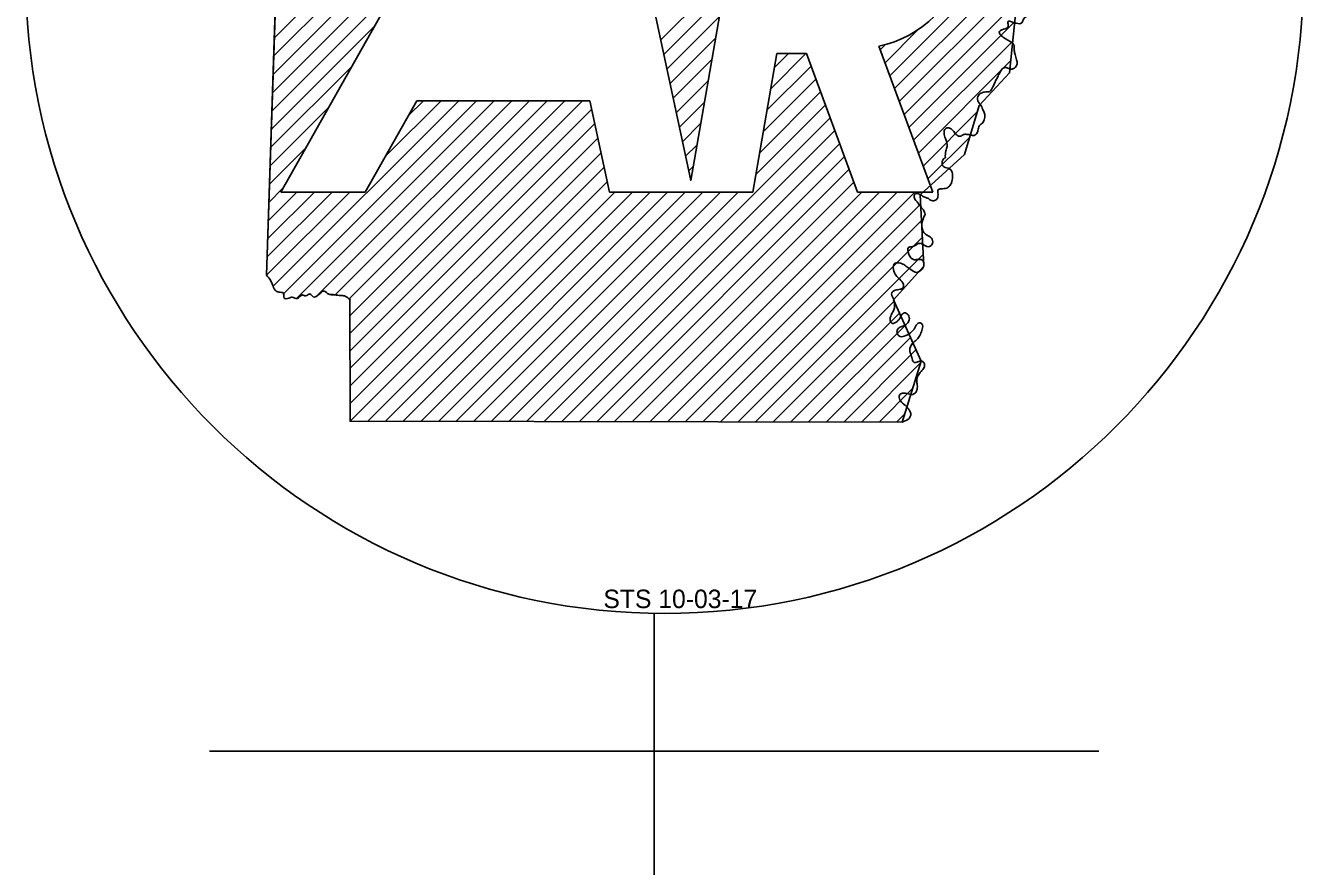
# Model space of a CAD drawing. Extents: x 1334737.7 to 1334827.2, y 402732.3 to 402753.5.
# Drawn here: x 1334746.2631 to 1334746.5859, y 402747.8449 to 402748.0573 of the extents above; entities that cross this region are included whole.
import ezdxf

# ---------------------------------------------------------------- set-up
doc = ezdxf.new("R2010")
doc.units = 0
doc.layers.add('R_Dimension', color=7, linetype='Continuous')
doc.layers.add('R_Draft', color=7, linetype='Continuous')

msp = doc.modelspace()

# ---------------------------------------------------------------- linework, layer by layer
at = {"layer": 'R_Dimension'}
for p, q in [((1334746.3259, 402748.05411), (1334746.38042, 402748.10863)), ((1334746.32575, 402748.04949), (1334746.3746, 402748.09834)), ((1334746.48142, 402748.04458), (1334746.53088, 402748.09403)), ((1334746.48263, 402748.04133), (1334746.53171, 402748.09041)), ((1334746.3256, 402748.04488), (1334746.36878, 402748.08806)), ((1334746.48383, 402748.03807), (1334746.53255, 402748.08678)), ((1334746.48504, 402748.03481), (1334746.53338, 402748.08315)), ((1334746.32544, 402748.04027), (1334746.36295, 402748.07778)), ((1334746.42355, 402748.05362), (1334746.44022, 402748.07029)), ((1334746.32529, 402748.03565), (1334746.35713, 402748.06749)), ((1334746.42434, 402748.04995), (1334746.43928, 402748.06489)), ((1334746.32514, 402748.03104), (1334746.35131, 402748.05721)), ((1334746.42512, 402748.04627), (1334746.43834, 402748.05949)), ((1334746.48624, 402748.03155), (1334746.513, 402748.05831)), ((1334746.42591, 402748.0426), (1334746.4374, 402748.05409)), ((1334746.48022, 402748.04784), (1334746.48871, 402748.05633)), ((1334746.47902, 402748.0511), (1334746.48037, 402748.05245)), ((1334746.48744, 402748.0283), (1334746.5125, 402748.05335)), ((1334746.4267, 402748.03892), (1334746.43646, 402748.04868)), ((1334746.45134, 402748.04126), (1334746.46025, 402748.05017)), ((1334746.45228, 402748.04666), (1334746.45579, 402748.05017)), ((1334746.48865, 402748.02504), (1334746.512, 402748.04839)), ((1334746.32498, 402748.02643), (1334746.34548, 402748.04693)), ((1334746.45039, 402748.03586), (1334746.46155, 402748.04701)), ((1334746.42748, 402748.03525), (1334746.43552, 402748.04328)), ((1334746.44945, 402748.03045), (1334746.46275, 402748.04375)), ((1334746.32564, 402747.9914), (1334746.37253, 402748.03828)), ((1334746.3283, 402747.98959), (1334746.37699, 402748.03828)), ((1334746.3315, 402747.98833), (1334746.38145, 402748.03828)), ((1334746.3368, 402747.98917), (1334746.38591, 402748.03828)), ((1334746.34133, 402747.98924), (1334746.39037, 402748.03828)), ((1334746.34482, 402747.98828), (1334746.39483, 402748.03828)), ((1334746.34497, 402747.98396), (1334746.39929, 402748.03828)), ((1334746.34498, 402747.97951), (1334746.40375, 402748.03828)), ((1334746.35394, 402748.02416), (1334746.36807, 402748.03828)), ((1334746.35977, 402748.03444), (1334746.36361, 402748.03828)), ((1334746.42827, 402748.03157), (1334746.43458, 402748.03788)), ((1334746.44851, 402748.02505), (1334746.46395, 402748.04049)), ((1334746.32483, 402748.02181), (1334746.33966, 402748.03664)), ((1334746.34499, 402747.97506), (1334746.4061, 402748.03617)), ((1334746.44757, 402748.01965), (1334746.46516, 402748.03724)), ((1334746.48985, 402748.02178), (1334746.50353, 402748.03546)), ((1334746.34501, 402747.97062), (1334746.40689, 402748.0325)), ((1334746.38964, 402747.95726), (1334746.46636, 402748.03398)), ((1334746.42905, 402748.0279), (1334746.43363, 402748.03248)), ((1334746.34502, 402747.96617), (1334746.40767, 402748.02882)), ((1334746.39409, 402747.95725), (1334746.46756, 402748.03072)), ((1334746.49105, 402748.01852), (1334746.50162, 402748.02909)), ((1334746.32468, 402748.0172), (1334746.33384, 402748.02636)), ((1334746.34503, 402747.96172), (1334746.40846, 402748.02515)), ((1334746.39854, 402747.95724), (1334746.46877, 402748.02747)), ((1334746.42984, 402748.02423), (1334746.43269, 402748.02708)), ((1334746.3451, 402747.95733), (1334746.40925, 402748.02147)), ((1334746.403, 402747.95724), (1334746.46997, 402748.02421)), ((1334746.43063, 402748.02055), (1334746.43175, 402748.02167)), ((1334746.40745, 402747.95723), (1334746.47117, 402748.02095)), ((1334746.32398, 402747.9942), (1334746.34501, 402748.01522)), ((1334746.32406, 402747.99874), (1334746.34055, 402748.01522)), ((1334746.32422, 402748.00336), (1334746.33609, 402748.01522)), ((1334746.32437, 402748.00797), (1334746.33163, 402748.01522)), ((1334746.32452, 402748.01258), (1334746.32801, 402748.01607)), ((1334746.34956, 402747.95732), (1334746.41003, 402748.0178)), ((1334746.35401, 402747.95732), (1334746.41192, 402748.01522)), ((1334746.35846, 402747.95731), (1334746.41638, 402748.01522)), ((1334746.36292, 402747.9573), (1334746.42084, 402748.01522)), ((1334746.36737, 402747.95729), (1334746.4253, 402748.01522)), ((1334746.37182, 402747.95729), (1334746.42976, 402748.01522)), ((1334746.37628, 402747.95728), (1334746.43422, 402748.01522)), ((1334746.38073, 402747.95727), (1334746.43868, 402748.01522)), ((1334746.38518, 402747.95726), (1334746.44314, 402748.01522)), ((1334746.4119, 402747.95722), (1334746.47238, 402748.01769)), ((1334746.41636, 402747.95721), (1334746.47437, 402748.01522)), ((1334746.42081, 402747.95721), (1334746.47883, 402748.01522)), ((1334746.42527, 402747.9572), (1334746.48329, 402748.01522)), ((1334746.42972, 402747.95719), (1334746.48775, 402748.01522)), ((1334746.43417, 402747.95718), (1334746.48924, 402748.01226)), ((1334746.43863, 402747.95718), (1334746.48944, 402748.008)), ((1334746.44308, 402747.95717), (1334746.48964, 402748.00374)), ((1334746.44753, 402747.95716), (1334746.48984, 402747.99947)), ((1334746.45199, 402747.95716), (1334746.48252, 402747.98769)), ((1334746.45644, 402747.95715), (1334746.48389, 402747.9846)), ((1334746.46089, 402747.95714), (1334746.48527, 402747.98152)), ((1334746.46535, 402747.95713), (1334746.48665, 402747.97844)), ((1334746.4698, 402747.95713), (1334746.48803, 402747.97535)), ((1334746.47425, 402747.95712), (1334746.48918, 402747.97204)), ((1334746.47871, 402747.95711), (1334746.48716, 402747.96556)), ((1334746.48316, 402747.9571), (1334746.48514, 402747.95909))]:
    msp.add_line(p, q, dxfattribs=at)
at = {"layer": 'R_Draft'}
for p, q in [((1334746.32753, 402748.01522), (1334746.38976, 402748.12512)), ((1334746.47867, 402748.05204), (1334746.49227, 402748.01522)), ((1334746.46038, 402748.05017), (1334746.45289, 402748.05017)), ((1334746.47329, 402748.01522), (1334746.46038, 402748.05017)), ((1334746.36194, 402748.03828), (1334746.34888, 402748.01522)), ((1334746.40565, 402748.03828), (1334746.36194, 402748.03828)), ((1334746.34888, 402748.01522), (1334746.32753, 402748.01522)), ((1334746.4468, 402748.01522), (1334746.41058, 402748.01522)), ((1334746.49227, 402748.01522), (1334746.47329, 402748.01522)), ((1334746.42189, 402747.49925), (1334746.42189, 402747.90883)), ((1334746.30953, 402747.87402), (1334746.53422, 402747.87402))]:
    msp.add_line(p, q, dxfattribs=at)
for points in [[(1334746.32392, 402747.99425), (1334746.32734, 402748.0975), (1334746.31946, 402748.16075)], [(1334746.54759, 402748.13423), (1334746.55291, 402748.12866), (1334746.53963, 402748.11775), (1334746.54107, 402748.10673), (1334746.52968, 402748.09922), (1334746.53358, 402748.08228), (1334746.5248, 402748.07428), (1334746.52402, 402748.06557), (1334746.51334, 402748.06173), (1334746.51168, 402748.0453), (1334746.50402, 402748.03709), (1334746.50031, 402748.02472), (1334746.48914, 402748.0145), (1334746.48999, 402747.99646), (1334746.4824, 402747.98795), (1334746.48931, 402747.97247), (1334746.48452, 402747.9571)], [(1334746.40825, 402748.12512), (1334746.43114, 402748.01816), (1334746.44578, 402748.10219)], [(1334746.32393, 402747.99424), (1334746.32626, 402748.06508)], [(1334746.45289, 402748.05017), (1334746.4468, 402748.01522)], [(1334746.41058, 402748.01522), (1334746.40565, 402748.03828)], [(1334746.48452, 402747.9571), (1334746.34504, 402747.95733), (1334746.34496, 402747.98812)], [(1334746.48451, 402747.95708), (1334746.34504, 402747.95733), (1334746.34498, 402747.98813)]]:
    msp.add_lwpolyline(points, dxfattribs=at)
msp.add_ellipse((1334746.4245, 402748.07024), major_axis=(0.16144, 0), ratio=0.999976, dxfattribs=at)
msp.add_ellipse((1334746.47293, 402748.07936), major_axis=(-0.02792, 0), ratio=0.999987, start_param=1.777838, end_param=4.099264, dxfattribs=at)
for points in [[(1334746.51656, 402748.05989), (1334746.51524, 402748.05888), (1334746.51464, 402748.05783), (1334746.51125, 402748.05814), (1334746.51135, 402748.05695), (1334746.51014, 402748.05632), (1334746.50907, 402748.05555), (1334746.50968, 402748.05462), (1334746.51083, 402748.05379), (1334746.51197, 402748.05315), (1334746.51268, 402748.05251), (1334746.51287, 402748.05092), (1334746.51308, 402748.04995), (1334746.51345, 402748.04856), (1334746.5136, 402748.04763), (1334746.51291, 402748.0465), (1334746.51211, 402748.04626), (1334746.51129, 402748.04653), (1334746.5103, 402748.0466), (1334746.5095, 402748.04586), (1334746.50893, 402748.04478), (1334746.50837, 402748.04369), (1334746.50793, 402748.0428), (1334746.50748, 402748.0418), (1334746.50669, 402748.04064), (1334746.50567, 402748.04048), (1334746.50444, 402748.04017), (1334746.50371, 402748.03935), (1334746.50383, 402748.03793), (1334746.50452, 402748.03698), (1334746.50504, 402748.03579), (1334746.50541, 402748.03477), (1334746.50525, 402748.03348), (1334746.50472, 402748.03251), (1334746.50402, 402748.03193), (1334746.50371, 402748.03073), (1334746.50321, 402748.0298), (1334746.50276, 402748.02952), (1334746.50186, 402748.02961), (1334746.50087, 402748.02978), (1334746.50003, 402748.02971), (1334746.49924, 402748.02929), (1334746.49842, 402748.02956), (1334746.49759, 402748.03046), (1334746.4969, 402748.03115), (1334746.49613, 402748.03143), (1334746.49532, 402748.03101), (1334746.4952, 402748.02973), (1334746.49559, 402748.02846), (1334746.49592, 402748.02669), (1334746.49559, 402748.02565), (1334746.49547, 402748.02386)], [(1334746.49547, 402748.02386), (1334746.49537, 402748.02382), (1334746.49469, 402748.02296), (1334746.49506, 402748.02161), (1334746.49655, 402748.02109), (1334746.49723, 402748.0198), (1334746.49726, 402748.01866), (1334746.49679, 402748.01709), (1334746.49609, 402748.01635), (1334746.49477, 402748.01605), (1334746.49375, 402748.01587), (1334746.4936, 402748.01412), (1334746.49312, 402748.01324), (1334746.49233, 402748.01298), (1334746.49118, 402748.01354), (1334746.49049, 402748.01384), (1334746.48966, 402748.01421), (1334746.48859, 402748.01482), (1334746.48778, 402748.01471), (1334746.48801, 402748.01305), (1334746.48809, 402748.01298), (1334746.48901, 402748.01172), (1334746.48991, 402748.01072), (1334746.49033, 402748.00955)], [(1334746.49547, 402748.02386), (1334746.49537, 402748.02382), (1334746.49469, 402748.02296), (1334746.49506, 402748.02161), (1334746.49655, 402748.02109), (1334746.49723, 402748.0198), (1334746.49726, 402748.01866), (1334746.49679, 402748.01709), (1334746.49609, 402748.01635), (1334746.49477, 402748.01605), (1334746.49375, 402748.01587), (1334746.4936, 402748.01412), (1334746.49312, 402748.01324), (1334746.49233, 402748.01298), (1334746.49118, 402748.01354), (1334746.49049, 402748.01384), (1334746.48966, 402748.01421), (1334746.48859, 402748.01482), (1334746.48778, 402748.01471), (1334746.48801, 402748.01305), (1334746.48809, 402748.01298), (1334746.48901, 402748.01172), (1334746.48991, 402748.01072), (1334746.49033, 402748.00955)], [(1334746.49033, 402748.00955), (1334746.48997, 402748.00866), (1334746.48953, 402748.00715), (1334746.48966, 402748.00586), (1334746.49024, 402748.00477), (1334746.49114, 402748.00415), (1334746.49215, 402748.00328), (1334746.49206, 402748.00193), (1334746.49148, 402748.00146), (1334746.49013, 402748.00177), (1334746.48911, 402748.00226), (1334746.48825, 402748.00198), (1334746.48709, 402748.00141), (1334746.4862, 402748.00126), (1334746.48624, 402747.99945), (1334746.4874, 402747.99816), (1334746.48842, 402747.99816), (1334746.48963, 402747.99802), (1334746.49004, 402747.99665), (1334746.48935, 402747.99549), (1334746.48822, 402747.99493), (1334746.48677, 402747.99563), (1334746.48575, 402747.99635), (1334746.48472, 402747.99703), (1334746.48343, 402747.99736), (1334746.48269, 402747.99723), (1334746.48235, 402747.99563), (1334746.48296, 402747.99418), (1334746.48394, 402747.99317), (1334746.48485, 402747.99189), (1334746.48472, 402747.99092), (1334746.48403, 402747.99067), (1334746.48281, 402747.9904), (1334746.48209, 402747.99003), (1334746.48191, 402747.98973), (1334746.48228, 402747.98842), (1334746.48261, 402747.98703), (1334746.48261, 402747.98594), (1334746.4822, 402747.98498), (1334746.48155, 402747.98347), (1334746.48163, 402747.98248), (1334746.48209, 402747.98199), (1334746.48265, 402747.98214), (1334746.48343, 402747.98267), (1334746.48392, 402747.98329), (1334746.48434, 402747.98406), (1334746.48512, 402747.98469), (1334746.48611, 402747.98412), (1334746.48634, 402747.98294), (1334746.48577, 402747.98193), (1334746.48497, 402747.98145), (1334746.484, 402747.98107), (1334746.48327, 402747.98025), (1334746.48344, 402747.97924), (1334746.48403, 402747.97871), (1334746.48545, 402747.97899), (1334746.48637, 402747.97942), (1334746.48693, 402747.97991), (1334746.48757, 402747.98057), (1334746.48789, 402747.98125), (1334746.4884, 402747.98193), (1334746.4893, 402747.98211), (1334746.48971, 402747.98155), (1334746.48953, 402747.98025), (1334746.48901, 402747.97901), (1334746.48828, 402747.978), (1334746.48749, 402747.97729), (1334746.4865, 402747.97572), (1334746.4867, 402747.97428), (1334746.48709, 402747.97306), (1334746.48758, 402747.97218), (1334746.48852, 402747.97236), (1334746.48953, 402747.97248), (1334746.49013, 402747.97199), (1334746.49008, 402747.97092), (1334746.48933, 402747.96987), (1334746.48859, 402747.9689), (1334746.48822, 402747.96754), (1334746.48837, 402747.96656), (1334746.48837, 402747.96572), (1334746.48807, 402747.96474), (1334746.48754, 402747.96422), (1334746.48611, 402747.96423), (1334746.48464, 402747.9644), (1334746.48385, 402747.96395), (1334746.484, 402747.96266), (1334746.48485, 402747.9617), (1334746.48546, 402747.96122), (1334746.48634, 402747.96015), (1334746.48672, 402747.95927), (1334746.48661, 402747.95851), (1334746.48606, 402747.95783), (1334746.48451, 402747.95708)], [(1334746.49033, 402748.00955), (1334746.48997, 402748.00866), (1334746.48953, 402748.00715), (1334746.48966, 402748.00586), (1334746.49024, 402748.00477), (1334746.49114, 402748.00415), (1334746.49215, 402748.00328), (1334746.49206, 402748.00193), (1334746.49148, 402748.00146), (1334746.49013, 402748.00177), (1334746.48911, 402748.00226), (1334746.48825, 402748.00198), (1334746.48709, 402748.00141), (1334746.4862, 402748.00126), (1334746.48624, 402747.99945), (1334746.4874, 402747.99816), (1334746.48842, 402747.99816), (1334746.48963, 402747.99802), (1334746.49004, 402747.99665), (1334746.48935, 402747.99549), (1334746.48822, 402747.99493), (1334746.48677, 402747.99563), (1334746.48575, 402747.99635), (1334746.48472, 402747.99703), (1334746.48343, 402747.99736), (1334746.48269, 402747.99723), (1334746.48235, 402747.99563), (1334746.48296, 402747.99418), (1334746.48394, 402747.99317), (1334746.48485, 402747.99189), (1334746.48472, 402747.99092), (1334746.48403, 402747.99067), (1334746.48281, 402747.9904), (1334746.48209, 402747.99003), (1334746.48191, 402747.98973), (1334746.48228, 402747.98842), (1334746.48261, 402747.98703), (1334746.48261, 402747.98594), (1334746.4822, 402747.98498), (1334746.48155, 402747.98347), (1334746.48163, 402747.98248), (1334746.48209, 402747.98199), (1334746.48265, 402747.98214), (1334746.48343, 402747.98267), (1334746.48392, 402747.98329), (1334746.48434, 402747.98406), (1334746.48512, 402747.98469), (1334746.48611, 402747.98412), (1334746.48634, 402747.98294), (1334746.48577, 402747.98193), (1334746.48497, 402747.98145), (1334746.484, 402747.98107), (1334746.48327, 402747.98025), (1334746.48344, 402747.97924), (1334746.48403, 402747.97871), (1334746.48545, 402747.97899), (1334746.48637, 402747.97942), (1334746.48693, 402747.97991), (1334746.48757, 402747.98057), (1334746.48789, 402747.98125), (1334746.4884, 402747.98193), (1334746.4893, 402747.98211), (1334746.48971, 402747.98155), (1334746.48953, 402747.98025), (1334746.48901, 402747.97901), (1334746.48828, 402747.978), (1334746.48749, 402747.97729), (1334746.4865, 402747.97572), (1334746.4867, 402747.97428), (1334746.48709, 402747.97306), (1334746.48758, 402747.97218), (1334746.48852, 402747.97236), (1334746.48953, 402747.97248), (1334746.49013, 402747.97199), (1334746.49008, 402747.97092), (1334746.48933, 402747.96987), (1334746.48859, 402747.9689), (1334746.48822, 402747.96754), (1334746.48837, 402747.96656), (1334746.48837, 402747.96572), (1334746.48807, 402747.96474), (1334746.48754, 402747.96422), (1334746.48611, 402747.96423), (1334746.48464, 402747.9644), (1334746.48385, 402747.96395), (1334746.484, 402747.96266), (1334746.48485, 402747.9617), (1334746.48546, 402747.96122), (1334746.48634, 402747.96015), (1334746.48672, 402747.95927), (1334746.48661, 402747.95851), (1334746.48606, 402747.95783), (1334746.48451, 402747.95708)], [(1334746.34496, 402747.98812), (1334746.34511, 402747.98804), (1334746.34439, 402747.98854), (1334746.3434, 402747.98903), (1334746.3423, 402747.98911), (1334746.34089, 402747.9893), (1334746.33971, 402747.98941), (1334746.33849, 402747.99021), (1334746.3372, 402747.98938), (1334746.33575, 402747.98877), (1334746.33491, 402747.98945), (1334746.33381, 402747.989), (1334746.33305, 402747.98922), (1334746.33172, 402747.98831), (1334746.33046, 402747.98865), (1334746.32955, 402747.98839), (1334746.32841, 402747.98842), (1334746.32818, 402747.98972), (1334746.32707, 402747.98991), (1334746.32612, 402747.99044), (1334746.32548, 402747.99177), (1334746.32502, 402747.9928), (1334746.32392, 402747.99425)], [(1334746.34498, 402747.98813), (1334746.34513, 402747.98805), (1334746.3444, 402747.98854), (1334746.3434, 402747.98903), (1334746.34229, 402747.9891), (1334746.34088, 402747.98929), (1334746.3397, 402747.9894), (1334746.3385, 402747.99021), (1334746.33721, 402747.98939), (1334746.33576, 402747.98876), (1334746.33491, 402747.98947), (1334746.33383, 402747.98899), (1334746.33305, 402747.98924), (1334746.33172, 402747.98831), (1334746.33045, 402747.98865), (1334746.32956, 402747.9884), (1334746.32842, 402747.98842), (1334746.32818, 402747.98973), (1334746.32706, 402747.9899), (1334746.32612, 402747.99044), (1334746.32548, 402747.99176), (1334746.32501, 402747.99282), (1334746.32393, 402747.99424)]]:
    msp.add_spline(points, degree=3, dxfattribs=at)

# ---------------------------------------------------------------- texts
msp.add_text('STS 10-03-17', height=0.0046674, dxfattribs=at).set_placement((1334746.40906, 402747.91013))

doc.saveas('drawing.dxf')
